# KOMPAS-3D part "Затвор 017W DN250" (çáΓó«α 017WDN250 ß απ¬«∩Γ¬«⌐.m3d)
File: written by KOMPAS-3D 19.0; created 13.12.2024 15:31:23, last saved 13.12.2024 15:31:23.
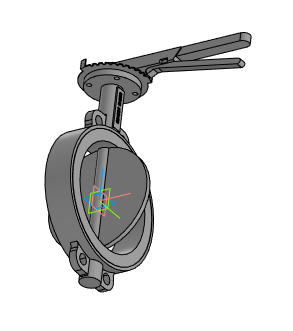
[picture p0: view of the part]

Document properties: Автор: Евгений; Полное имя файла: ..\Затвор 017WDN250.a3d

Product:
- Part/product: Затвор 017W DN250
    Масса: 29.7564

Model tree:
1. Операция без истории:1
